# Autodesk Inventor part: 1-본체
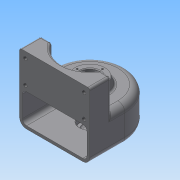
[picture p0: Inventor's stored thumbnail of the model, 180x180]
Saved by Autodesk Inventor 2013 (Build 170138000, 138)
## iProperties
Created: 2015-02
Part Number: 1-본체
Material: 일반
Document SubType Name: Modeling
Designer: Administrator
Density: 1 g/cm^3
Author: Administrator
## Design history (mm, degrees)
sketch "스케치1"
  geometry: L1 (-50, 0)-(50, 0); L2 (50, 0)-(50, -50); L3 (50, -50)-(-50, -50); L4 (-50, -50)-(-50, 0); A1 r 50 centre (0, 0) between (-50, 0) and (0, -50); 1 further point
  constraints: 8 end point, 2 parallel, 2 point on circle, 1 centre point, 1 coincident, 1 horizontal, 1 midpoint, 1 perpendicular
  dimensions: "d0" = 50 radius of A1; "d2" = 50 distance from line of L3 point (0, 0); "d3" = 100 distance of L1.start L1.end
extrude "돌출1" new body sketch "스케치1" distance "d4" = 50; taper "d5" = 0 deg
feature "쉘1" dims "d19" = 4
sketch "스케치2"
  geometry: L1 (-50, 0)-(-50, -50) reference; L2 (-50, -50)-(50, -50) reference; L3 (50, -50)-(50, 0) reference; L4 (-50, -20)-(-34.641, -20); L5 (50, -20)-(34.641, -20); A1 r 50 centre (0, 0) between (50, 0) and (-50, 0) reference; A2 r 40 centre (0, 0) between (-34.641, -20) and (34.641, -20)
  constraints: 4 end point, 2 perpendicular, 2 point on circle, 2 point on line, 1 centre point, 1 coincident, 1 collinear
  dimensions: "d6" = 40 radius of A2; "d8" = 30 distance between parallel lines of L2 L5
extrude "돌출2" join sketch "스케치2" distance "d9" = 45; taper "d10" = 0 deg
sketch "스케치3"
  geometry: C1 r 25 at (0, 0); A1 r 40 centre (0, 0) between (-34.641, -20) and (34.641, -20) reference
  constraints: 1 centre point, 1 coincident
  dimensions: "d11" = 50 diameter of C1
extrude "돌출3" join sketch "스케치3" distance "d13" = 10; taper "d14" = -20 deg
sketch "스케치6"
  geometry: C1 r 20 at (0, 0); A1 r 50 centre (0, 0) between (50, 0) and (-50, 0) reference
  constraints: 1 centre point, 1 coincident
  dimensions: "d25" = 40 diameter of C1
extrude "돌출6" join sketch "스케치6" distance "d27" = 9; taper "d28" = 0 deg
hole "구멍1" diameter "d31" = 20; stored, may be unused: countersink angle "d35" = 90 deg, drill point angle "d37" = 0 deg; dims "d32" = 6, "d33" = 28, "d34" = 10, "d36" = 14, "d49" = 10, "d50" = 10
hole "구멍2" diameter "d40" = 20; stored, may be unused: countersink angle "d44" = 90 deg, drill point angle "d46" = 0 deg; dims "d41" = 6, "d42" = 28, "d43" = 8, "d45" = 10, "d47" = 10, "d48" = 10
sketch "스케치7"
  geometry: L1 (0, 95)-(100, 95) reference; L2 (8.25, 86)-(91.75, 86); L3 (91.75, 86)-(91.75, 53); L4 (91.75, 53)-(8.25, 53); L5 (8.25, 53)-(8.25, 86); 7 further points
  constraints: 8 end point, 4 coincident, 2 midpoint, 2 parallel, 1 horizontal, 1 perpendicular, 1 vertical alignment
  dimensions: "d51" = 83.5 distance of L2.start L2.end; "d53" = 33 distance of L4.end L2.start; "d54" = 9 distance between parallel lines of L2 L1
hole "구멍3" sketch "스케치7" at (91.75, 86), (91.75, 53), (8.25, 53), (8.25, 86) diameter "d55" = 5.134; stored, may be unused: countersink angle "d59" = 90 deg, drill point angle "d61" = 118 deg; dims "d56" = 10, "d57" = 28, "d58" = 8, "d60" = 13
sketch "스케치8"
  geometry: C1 r 14 at (0, 0) reference; C2 r 21.36 at (0, 0) reference; A1 r 18 centre (0, 0) between (0, 18) and (-18, 0); 3 further points
  constraints: 4 point on circle, 2 coincident, 2 horizontal alignment, 2 vertical alignment, 1 centre point
  dimensions: "d62" = 36 diameter of A1
hole "구멍4" sketch "스케치8" at (0, 18), (-18, 0), (18, 0), (0, -18) diameter "d64" = 2.459; stored, may be unused: countersink angle "d68" = 90 deg, drill point angle "d70" = 118 deg; dims "d65" = 6, "d66" = 28, "d67" = 8, "d69" = 9
node "작업 평면1"
sketch "스케치9"
  geometry: L1 (50, 0)-(-50, 0) reference; 3 further points
  constraints: 1 midpoint, 1 vertical alignment, 1 other
  dimensions: "d71" = 25 distance from line of point (0, 25) L1
feature "엠보싱1" sketch "스케치9" dims "d0" = 50, "d2" = 50, "d3" = 100, "d72" = 0.5, "d73" = 0
fillet "모깎기2" dims "d74" = 0.3, "d75" = 3, "d76" = 6
fillet "모깎기3" dims "d77" = 3, "d78" = 10
chamfer "모따기1" distance "d79" = 1; stored, may be unused: second distance "d80" = 2, angle "d81" = 45 deg
node "솔리드1"
